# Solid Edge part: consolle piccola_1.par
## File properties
Last saved by: i.fialdini
Revision: 62
Tipo di contenuto documento: 0
Accuracy: 0.990
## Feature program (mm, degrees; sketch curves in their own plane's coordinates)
body "unnamed Body 1"
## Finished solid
Body 1: solid body, 3 faces, 4 edges, 4 vertices.
  Faces by surface: cylinder 3
  Edges by curve: ellipse 4
Bounding box of the edges (mm): 21.000 x 425.000 x 21.000, from (-185.5, -928.6568, 681.9818) to (-164.5, -503.6568, 702.9818).
Cylindrical faces by radius (mm): R10.5 x3
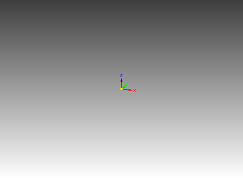
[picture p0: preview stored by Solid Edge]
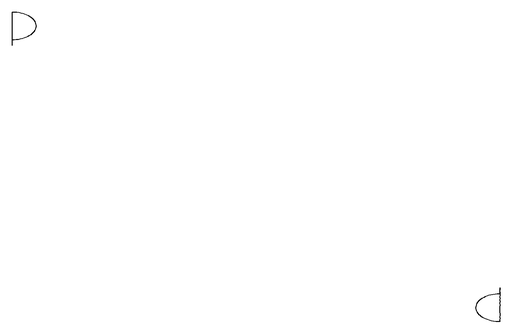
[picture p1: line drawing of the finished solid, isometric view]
